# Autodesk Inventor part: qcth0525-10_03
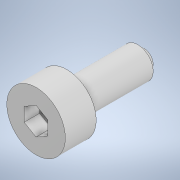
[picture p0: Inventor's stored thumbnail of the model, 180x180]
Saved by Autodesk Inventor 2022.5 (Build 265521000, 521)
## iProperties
Created: 2022-02
Part Number: qcth0525-10_03
Material: 一般
Document SubType Name: Modeling
Designer: ImaoCorp
Density: 1 g/cm^3
Appearance: 既定
Author: ImaoCorp
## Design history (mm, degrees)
feature "qcth0525-10_03"
node "ソリッド1"
